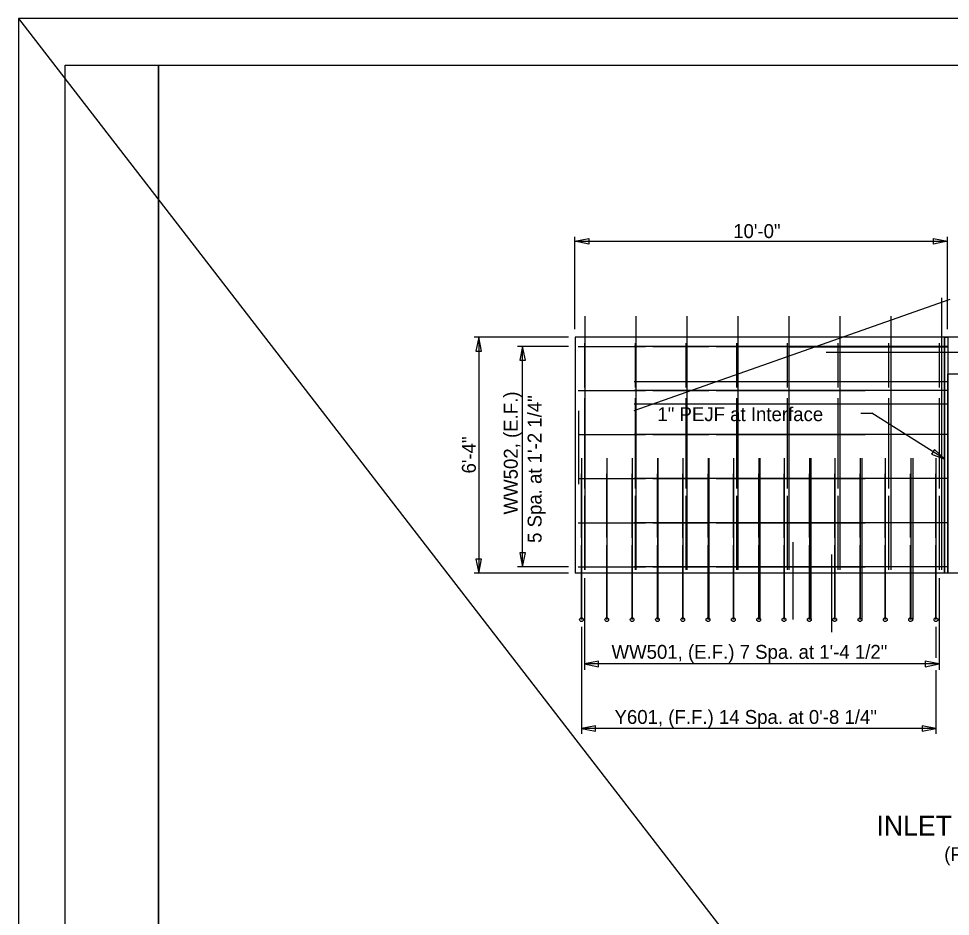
# Model space of a CAD drawing. Extents: x -1609 to 1184, y -412 to 394.
# Drawn here: x -1126.89 to -1101.88, y -67.94 to -43.84 of the extents above; entities that cross this region are included whole.
import ezdxf

# ---------------------------------------------------------------- set-up
doc = ezdxf.new("R2010")
doc.units = 0
for name, color, linetype in [('DR_P_Culvert', 7, 'Continuous'), ('SH_Border', 7, 'Continuous'), ('SH_Cut_Line', 7, 'Continuous'), ('ST_Details', 7, 'Continuous'), ('ST_Text', 7, 'Continuous'), ('XS_P_Finished_Grade', 7, 'Continuous')]:
    doc.layers.add(name, color=color, linetype=linetype)

msp = doc.modelspace()

# ---------------------------------------------------------------- linework, layer by layer
at = {"layer": 'DR_P_Culvert'}
for p, q in [((-1102.035, -52.391), (-1102.035, -58.724)), ((-1101.951, -52.391), (-1101.951, -58.724)), ((-1096.279, -52.807), (-1105.214, -52.807)), ((-1106.112, -57.89), (-1106.112, -59.974)), ((-1105.071, -58.223), (-1105.071, -60.307))]:
    msp.add_line(p, q, dxfattribs=at)
msp.add_lwpolyline([(-1102.035, -52.391), (-1101.951, -52.391), (-1101.951, -58.724), (-1102.035, -58.724)], close=True, dxfattribs=at)
at = {"layer": 'SH_Border'}
for points in [[(-1125.641, -45.094), (-1123.141, -45.094), (-1123.141, -97.594), (-1125.641, -97.594)], [(-1123.141, -45.094), (-1043.141, -45.094), (-1043.141, -97.594), (-1123.141, -97.594)]]:
    msp.add_lwpolyline(points, close=True, dxfattribs=at)
at = {"layer": 'SH_Cut_Line'}
msp.add_lwpolyline([(-1126.891, -98.844), (-1041.891, -98.844), (-1041.891, -43.844), (-1126.891, -43.844)], close=True, dxfattribs=at)
at = {"layer": 'ST_Details'}
for p, q in [((-1101.895, -51.381), (-1110.377, -54.374)), ((-1102.117, -51.341), (-1102.117, -58.64)), ((-1111.689, -51.827), (-1111.689, -58.64)), ((-1110.321, -51.827), (-1110.321, -58.64)), ((-1108.954, -51.827), (-1108.954, -58.64)), ((-1107.586, -51.827), (-1107.586, -58.64)), ((-1106.218, -51.827), (-1106.218, -58.64)), ((-1104.851, -51.827), (-1104.851, -58.64)), ((-1103.483, -51.827), (-1103.483, -58.64)), ((-1111.951, -52.391), (-1111.951, -58.724)), ((-1101.951, -52.391), (-1111.951, -52.391)), ((-1097.279, -52.391), (-1101.951, -52.391)), ((-1111.701, -52.557), (-1111.701, -53.744)), ((-1101.951, -52.641), (-1110.367, -52.641)), ((-1110.342, -52.557), (-1110.342, -53.744)), ((-1108.982, -52.557), (-1108.982, -53.744)), ((-1107.623, -52.557), (-1107.623, -53.744)), ((-1106.263, -52.557), (-1106.263, -53.744)), ((-1101.951, -52.665), (-1106.187, -52.665)), ((-1104.904, -52.557), (-1104.904, -53.744)), ((-1103.545, -52.557), (-1103.545, -53.744)), ((-1102.185, -52.557), (-1102.185, -53.744)), ((-1101.951, -58.724), (-1101.951, -53.39)), ((-1097.279, -53.39), (-1101.951, -53.39)), ((-1101.951, -53.593), (-1110.367, -53.593)), ((-1101.951, -53.824), (-1110.367, -53.824)), ((-1101.951, -54.193), (-1110.367, -54.193)), ((-1111.867, -54.371), (-1111.867, -56.342)), ((-1101.951, -55.007), (-1110.367, -55.007)), ((-1111.784, -55.64), (-1111.784, -59.974)), ((-1111.1, -55.64), (-1111.1, -59.974)), ((-1110.425, -55.64), (-1110.425, -59.974)), ((-1109.741, -55.64), (-1109.741, -59.974)), ((-1109.733, -55.64), (-1109.733, -59.974)), ((-1109.065, -55.64), (-1109.065, -59.974)), ((-1108.382, -55.64), (-1108.382, -59.974)), ((-1108.365, -55.64), (-1108.365, -59.974)), ((-1107.706, -55.64), (-1107.706, -59.974)), ((-1107.022, -55.64), (-1107.022, -59.974)), ((-1106.997, -55.64), (-1106.997, -59.974)), ((-1106.347, -55.64), (-1106.347, -59.974)), ((-1105.663, -55.64), (-1105.663, -59.974)), ((-1105.63, -55.64), (-1105.63, -59.974)), ((-1104.987, -55.64), (-1104.987, -59.974)), ((-1104.303, -55.64), (-1104.303, -59.974)), ((-1104.262, -55.64), (-1104.262, -59.974)), ((-1103.628, -55.64), (-1103.628, -59.974)), ((-1102.944, -55.64), (-1102.944, -59.974)), ((-1102.893, -55.641), (-1102.893, -59.974)), ((-1102.268, -55.64), (-1102.268, -59.974)), ((-1111.784, -57.774), (-1111.784, -56.057)), ((-1111.104, -57.773), (-1111.104, -56.057)), ((-1110.425, -57.774), (-1110.425, -56.057)), ((-1101.951, -56.19), (-1110.367, -56.19)), ((-1109.745, -57.773), (-1109.745, -56.057)), ((-1109.065, -57.774), (-1109.065, -56.057)), ((-1108.386, -57.773), (-1108.386, -56.057)), ((-1107.706, -57.774), (-1107.706, -56.057)), ((-1107.026, -57.773), (-1107.026, -56.057)), ((-1106.347, -57.774), (-1106.347, -56.057)), ((-1105.667, -57.773), (-1105.667, -56.057)), ((-1104.987, -57.774), (-1104.987, -56.057)), ((-1104.307, -57.773), (-1104.307, -56.057)), ((-1103.628, -57.774), (-1103.628, -56.057)), ((-1102.948, -57.773), (-1102.948, -56.057)), ((-1102.268, -57.774), (-1102.268, -56.057)), ((-1101.951, -57.374), (-1110.367, -57.374)), ((-1101.951, -58.724), (-1111.951, -58.724)), ((-1101.951, -58.557), (-1110.367, -58.557)), ((-1097.279, -58.724), (-1101.951, -58.724))]:
    msp.add_line(p, q, dxfattribs=at)
for points in [[(-1111.868, -52.641), (-1110.068, -52.641)], [(-1109.868, -52.641), (-1108.367, -52.641)], [(-1108.167, -52.641), (-1104.167, -52.641)], [(-1102.034, -52.641), (-1103.951, -52.641)], [(-1111.868, -53.824), (-1110.068, -53.824)], [(-1109.868, -53.824), (-1108.367, -53.824)], [(-1108.167, -53.824), (-1104.167, -53.824)], [(-1102.034, -53.824), (-1103.951, -53.824)], [(-1111.701, -54.027), (-1111.701, -56.456)], [(-1110.342, -54.027), (-1110.342, -56.456)], [(-1108.982, -54.027), (-1108.982, -56.456)], [(-1107.623, -54.027), (-1107.623, -56.456)], [(-1106.263, -54.027), (-1106.263, -56.456)], [(-1104.904, -54.027), (-1104.904, -56.456)], [(-1103.545, -54.027), (-1103.545, -56.456)], [(-1102.185, -54.027), (-1102.185, -56.456)], [(-1111.868, -55.007), (-1110.068, -55.007)], [(-1109.868, -55.007), (-1108.367, -55.007)], [(-1108.167, -55.007), (-1104.167, -55.007)], [(-1102.034, -55.007), (-1103.951, -55.007)], [(-1111.868, -56.19), (-1110.068, -56.19)], [(-1109.868, -56.19), (-1108.367, -56.19)], [(-1108.167, -56.19), (-1104.167, -56.19)], [(-1102.034, -56.19), (-1103.951, -56.19)], [(-1111.701, -56.65), (-1111.701, -58.64)], [(-1110.342, -56.65), (-1110.342, -58.64)], [(-1108.982, -56.65), (-1108.982, -58.64)], [(-1107.623, -56.65), (-1107.623, -58.64)], [(-1106.263, -56.65), (-1106.263, -58.64)], [(-1104.904, -56.65), (-1104.904, -58.64)], [(-1103.545, -56.65), (-1103.545, -58.64)], [(-1102.185, -56.65), (-1102.185, -58.64)], [(-1111.868, -57.374), (-1110.068, -57.374)], [(-1109.868, -57.374), (-1108.367, -57.374)], [(-1108.167, -57.374), (-1104.167, -57.374)], [(-1102.034, -57.374), (-1103.951, -57.374)], [(-1111.784, -59.974), (-1111.784, -57.974)], [(-1111.104, -59.973), (-1111.104, -57.973)], [(-1110.425, -59.974), (-1110.425, -57.974)], [(-1109.745, -59.973), (-1109.745, -57.973)], [(-1109.065, -59.974), (-1109.065, -57.974)], [(-1108.386, -59.973), (-1108.386, -57.973)], [(-1107.706, -59.974), (-1107.706, -57.974)], [(-1107.026, -59.973), (-1107.026, -57.973)], [(-1106.347, -59.974), (-1106.347, -57.974)], [(-1105.667, -59.973), (-1105.667, -57.973)], [(-1104.987, -59.974), (-1104.987, -57.974)], [(-1104.307, -59.973), (-1104.307, -57.973)], [(-1103.628, -59.974), (-1103.628, -57.974)], [(-1102.948, -59.973), (-1102.948, -57.973)], [(-1102.268, -59.974), (-1102.268, -57.974)], [(-1111.868, -58.557), (-1110.068, -58.557)], [(-1109.868, -58.557), (-1108.367, -58.557)], [(-1108.167, -58.557), (-1104.167, -58.557)], [(-1102.034, -58.557), (-1103.951, -58.557)]]:
    msp.add_lwpolyline(points, dxfattribs=at)
for centre in [(-1111.784, -59.974), (-1111.104, -59.974), (-1110.425, -59.974), (-1109.745, -59.974), (-1109.065, -59.974), (-1108.386, -59.974), (-1107.706, -59.974), (-1107.026, -59.974), (-1106.347, -59.974), (-1105.667, -59.974), (-1104.987, -59.974), (-1104.307, -59.974), (-1103.628, -59.974), (-1102.948, -59.974), (-1102.268, -59.974)]:
    msp.add_circle(centre, 0.0502, dxfattribs=at)
at = {"layer": 'ST_Text'}
for p, q in [((-1111.961, -52.178), (-1111.961, -49.7)), ((-1101.961, -52.178), (-1101.961, -49.7)), ((-1111.961, -49.818), (-1101.961, -49.818)), ((-1112.129, -52.391), (-1114.664, -52.391)), ((-1114.541, -52.391), (-1114.541, -58.724)), ((-1112.129, -52.641), (-1113.502, -52.641)), ((-1113.364, -58.557), (-1113.364, -52.641)), ((-1104.287, -54.429), (-1103.992, -54.429)), ((-1102.028, -55.666), (-1103.992, -54.429)), ((-1112.129, -58.724), (-1114.664, -58.724)), ((-1112.129, -58.557), (-1113.502, -58.557)), ((-1111.701, -58.86), (-1111.701, -61.321)), ((-1102.185, -58.863), (-1102.185, -61.321)), ((-1111.784, -60.167), (-1111.784, -63.034)), ((-1102.268, -60.167), (-1102.268, -60.999)), ((-1102.185, -61.164), (-1111.701, -61.164)), ((-1102.268, -61.333), (-1102.268, -63.034)), ((-1102.268, -62.897), (-1111.784, -62.897))]:
    msp.add_line(p, q, dxfattribs=at)
for points in [[(-1111.587, -49.893), (-1111.961, -49.818), (-1111.587, -49.744)], [(-1102.334, -49.744), (-1101.961, -49.818), (-1102.334, -49.893)], [(-1114.467, -52.764), (-1114.541, -52.391), (-1114.616, -52.764)], [(-1113.29, -53.014), (-1113.364, -52.64), (-1113.439, -53.014)], [(-1102.385, -55.534), (-1102.028, -55.666), (-1102.307, -55.407)], [(-1113.439, -58.184), (-1113.364, -58.557), (-1113.29, -58.184)], [(-1114.616, -58.35), (-1114.541, -58.724), (-1114.467, -58.35)], [(-1111.328, -61.09), (-1111.701, -61.164), (-1111.328, -61.239)], [(-1102.559, -61.239), (-1102.185, -61.164), (-1102.559, -61.09)], [(-1111.411, -62.822), (-1111.784, -62.897), (-1111.411, -62.971)], [(-1102.642, -62.971), (-1102.268, -62.897), (-1102.642, -62.822)]]:
    msp.add_lwpolyline(points, close=True, dxfattribs=at)
at = {"layer": 'XS_P_Finished_Grade'}
msp.add_line((-1126.891, -43.844), (-1041.891, -153.844), dxfattribs=at)

# ---------------------------------------------------------------- texts
at = {"layer": 'ST_Text'}
for s, height, p in [('10\'-0"', 0.3733, (-1107.711, -49.733)), ('1" PEJF at Interface', 0.37335, (-1109.745, -54.646)), ('WW501, (E.F.) 7 Spa. at 1\'-4 1/2"', 0.37335, (-1110.977, -61.025)), ('Y601, (F.F.) 14 Spa. at 0\'-8 1/4"', 0.37335, (-1110.896, -62.772)), ('INLET WINGWALL ELEVATION', 0.53335, (-1103.863, -65.77)), ('(FOOTING NOT SHOWN FOR CLARITY)', 0.37335, (-1102.046, -66.455))]:
    msp.add_text(s, height=height, dxfattribs=at).set_placement(p)
for s, height, p in [('WW502, (E.F.)', 0.37335, (-1113.494, -57.151)), ('5 Spa. at 1\'-2 1/4"', 0.37335, (-1112.854, -57.915)), ('6\'-4"', 0.3733, (-1114.619, -56.051))]:
    msp.add_text(s, height=height, rotation=90, dxfattribs=at).set_placement(p)

doc.saveas('drawing.dxf')
